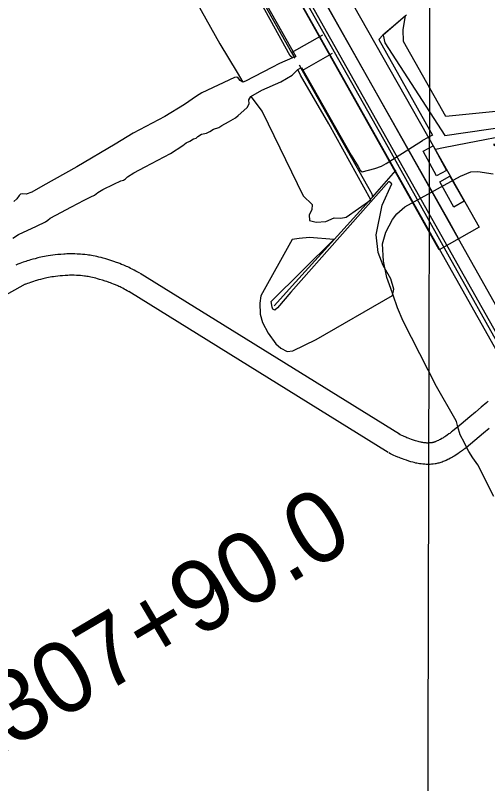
# Model space of a CAD drawing. Extents: x 3177185 to 3215018, y 812988 to 838321.
# Drawn here: x 3191262 to 3191925, y 825495 to 826573 of the extents above; entities that cross this region are included whole.
import ezdxf

# ---------------------------------------------------------------- set-up
doc = ezdxf.new("R2010")
doc.units = 0
for name, color, linetype in [('V-BLDG-OTLN', 7, 'Continuous'), ('V-BRDG-OTLN', 7, 'Continuous'), ('V-FLOD-BASE', 7, 'Continuous'), ('V-GRID-MAJR', 7, 'Continuous'), ('V-LEVE-TOET', 7, 'Continuous'), ('V-RAIL-TRAK', 7, 'Continuous'), ('V-RIVR-JETY', 7, 'Continuous'), ('V-ROAD-CNTR', 7, 'Continuous'), ('V-SURV-IDEN', 7, 'Continuous'), ('V-SURV-LINE', 7, 'Continuous'), ('V-TOPO-SHOR', 7, 'Continuous')]:
    doc.layers.add(name, color=color, linetype=linetype)

msp = doc.modelspace()

# ---------------------------------------------------------------- linework, layer by layer
at = {"layer": 'V-BLDG-OTLN'}
for points in [[(3191853.342, 826348.125), (3191834.697, 826382.585), (3191848.629, 826390.126), (3191867.278, 826355.664)], [(3191857.919, 826339.643), (3191872.198, 826347.675), (3191892.082, 826312.328), (3191877.801, 826304.296)]]:
    msp.add_lwpolyline(points, close=True, dxfattribs=at)
at = {"layer": 'V-BRDG-OTLN'}
msp.add_lwpolyline([(3189931.128, 829788.835), (3190041.103, 829594.308), (3190262.136, 829203.113), (3190443.982, 828880.4280000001), (3190572.68, 828651.763), (3190882.977, 828101.979), (3191302.909, 827356.358), (3191715.392, 826625.533), (3191850.532, 826386.759), (3191913.1350000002, 826276.1460000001), (3191857.18, 826244.404), (3191504.1350000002, 826872.585), (3191185.7430000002, 827436.355), (3190860.389, 828014.278), (3190535.683, 828590.2490000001), (3190389.4390000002, 828848.387), (3190198.296, 829187.503), (3189983.563, 829569.502), (3189815.178, 829866.551), (3189869.727, 829897.438)], close=True, dxfattribs=at)
msp.add_lwpolyline([(3189842.421, 829881.978), (3189906.728, 829766.487), (3190091.396, 829438.875), (3190276.556, 829111.594), (3190415.058, 828865.636), (3190768.106, 828239.242), (3190952.4020000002, 827910.9990000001), (3191133.947, 827589.914), (3191349.986, 827207.018), (3191641.818, 826689.277), (3191870.9790000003, 826283.448), (3191884.369, 826259.828)], dxfattribs=at)
at = {"layer": 'V-FLOD-BASE'}
for p, q in [((3191649.643, 826521.356), (3191693.649, 826546.165)), ((3191649.643, 826521.356), (3191654.1350000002, 826513.3520000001)), ((3191664.829, 826495.9890000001), (3191707.4220000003, 826520.448)), ((3191660.455, 826503.755), (3191664.829, 826495.9890000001))]:
    msp.add_line(p, q, dxfattribs=at)
for points in [[(3190314.173, 828890.916), (3190510.294, 828542.9940000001), (3190730.057, 828152.9400000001), (3191049.907, 827586.404), (3191280.358, 827177.3200000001), (3191576.724, 826651.285), (3191649.643, 826521.356)], [(3191664.829, 826495.9890000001), (3191762.482, 826322.716), (3191763.287, 826318.327)], [(3191850.532, 826386.759), (3191851.992, 826385.295), (3191863.3710000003, 826387.709), (3191896.6920000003, 826394.31), (3192023.1520000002, 826418.607), (3192066.715, 826427.301), (3192080.043, 826429.388)], [(3191625.213, 826165.849), (3191655.335, 826198.941), (3191718.997, 826268.851), (3191763.287, 826318.327), (3191796.014, 826355.638), (3191795.0470000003, 826354.958)]]:
    msp.add_lwpolyline(points, dxfattribs=at)
at = {"layer": 'V-GRID-MAJR'}
msp.add_spline([(3191823.847, 818374.883), (3191838.828, 824434.0750000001), (3191853.818, 830496.351), (3191868.808, 836558.667), (3191868.816, 836561.711)], degree=3, dxfattribs=at)
at = {"layer": 'V-LEVE-TOET'}
msp.add_lwpolyline([(3191933.722, 825898.231), (3191911.382, 825942.632), (3191904.576, 825952.231), (3191898.906, 825961.34), (3191895.342, 825967.197), (3191892.592, 825973.376), (3191886.599, 825984.761), (3191883.3710000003, 825995.816), (3191881.272, 826003.457), (3191879.005, 826007.361), (3191853.417, 826052.581), (3191806.631, 826143.985), (3191798.703, 826163.011), (3191792.563, 826180.732), (3191789.3310000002, 826190.1630000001), (3191783.673, 826205.286), (3191779.003, 826228.528), (3191777.2600000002, 826252.7440000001), (3191782.329, 826269.144), (3191791.3000000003, 826287.001), (3191797.489, 826294.951), (3191808.718, 826304.679), (3191886.953, 826347.755), (3191901.752, 826353.7390000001), (3191911.177, 826354.372), (3191932.782, 826350.755)], dxfattribs=at)
at = {"layer": 'V-RAIL-TRAK'}
for points in [[(3191871.696, 826233.868), (3191785.219, 826388.248), (3191407.875, 827056.285), (3191034.9080000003, 827717.65), (3190723.6380000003, 828268.084), (3190388.417, 828864.737)], [(3193727.307, 822943), (3193577.661, 823206.018), (3193415.878, 823494.571), (3193219.921, 823842.66), (3193027.524, 824182.939), (3192797.072, 824592.348), (3192558.2, 825016.721), (3192352.2, 825381.723), (3192184.2600000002, 825679.875), (3191974.37, 826050.574), (3191871.696, 826233.868)]]:
    msp.add_lwpolyline(points, dxfattribs=at)
at = {"layer": 'V-RIVR-JETY'}
for p, q in [((3191809.662, 826572.605), (3191778.235, 826545.731)), ((3191651.306, 826513.821), (3191651.294, 826513.831))]:
    msp.add_line(p, q, dxfattribs=at)
for points in [[(3191651.239, 826513.79), (3191647.901, 826516.692), (3191568.704, 826660.794), (3191407.398, 826948.171), (3191228.251, 827262.207), (3190970.738, 827718.264), (3190670.929, 828250.537), (3190397.24, 828734.5), (3190316.142, 828880.123)], [(3190290.572, 828778.2390000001), (3190397.9390000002, 828569.5970000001), (3190618.136, 828181.843), (3190879.796, 827718.289), (3191104.97, 827320.956), (3191323.508, 826935.701), (3191549.0870000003, 826533.373), (3191573.142, 826492.9720000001), (3191581.4020000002, 826479.777)], [(3191933.285, 826391.953), (3192060.863, 826312.2490000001), (3192152.944, 826383.2220000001), (3192074.849, 826448.688), (3192064.038, 826452.037), (3192054.883, 826451.638), (3192025.3370000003, 826447.116), (3191866.375, 826431.186), (3191807.077, 826536.56), (3191806.6920000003, 826553.618), (3191809.662, 826572.605)], [(3191778.235, 826545.731), (3191780.842, 826534.665), (3191865.058, 826404.699), (3192081.4620000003, 826435.915), (3192085.603, 826425.089), (3191933.285, 826391.953)], [(3191651.239, 826513.79), (3191632.96, 826505.6780000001), (3191622.225, 826500.1730000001)], [(3191622.225, 826500.1730000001), (3191584.816, 826480.746), (3191581.4020000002, 826479.777)], [(3191592.576, 826459.444), (3191608.497, 826438.4770000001), (3191666.107, 826320.211), (3191678.565, 826307.706), (3191678.1350000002, 826300.219), (3191674.377, 826293.569), (3191674.779, 826285.248), (3191684.345, 826283.149), (3191697.659, 826283.958), (3191709.734, 826289.344), (3191718.886, 826288.91), (3191726.378, 826290.145), (3191760.9560000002, 826314.626), (3191702.076, 826421.245), (3191662.2630000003, 826489.552), (3191658.491, 826497.099)], [(3191634.535, 826480.002), (3191650.477, 826489.3960000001), (3191657.5470000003, 826496.536), (3191658.491, 826497.099)], [(3191592.576, 826459.444), (3191608.028, 826468.191), (3191634.535, 826480.002)], [(3191650.538, 826258.513), (3191606.705, 826179.546), (3191605.024, 826169.564), (3191605.411, 826154.17), (3191608.716, 826142.099), (3191617.009, 826127.103), (3191627.384, 826112.524), (3191634.861, 826106.269), (3191643.588, 826101.675), (3191651.495, 826102.492), (3191684.392, 826118.242), (3191791.433, 826180.032), (3191793.5300000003, 826189.182), (3191788.9790000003, 826203.336), (3191778.614, 826222.077), (3191771.16, 826240.399), (3191768.71, 826265.366), (3191777.109, 826306.954), (3191790.478, 826336.886), (3191786.325, 826340.2220000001), (3191648.736, 826184.875), (3191629.972, 826162.859), (3191626.223, 826159.539), (3191623.312, 826160.7930000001), (3191622.487, 826163.7050000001), (3191621.252, 826171.6140000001), (3191709.201, 826258.8200000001), (3191675.065, 826261.46)], [(3191675.065, 826261.46), (3191660.502, 826260.24), (3191650.538, 826258.513)]]:
    msp.add_lwpolyline(points, dxfattribs=at)
at = {"layer": 'V-ROAD-CNTR'}
for points in [[(3186813.0193371, 835225.176522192), (3189830.7133017, 829864.116244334), (3191892.325178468, 826207.063558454)], [(3191436.466090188, 826211.367549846), (3191433.683095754, 826212.9725466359), (3191430.952101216, 826214.4835436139), (3191428.38510635, 826215.85054088), (3191425.9691111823, 826217.0905384), (3191423.696115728, 826218.2165361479), (3191421.561119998, 826219.239534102), (3191419.553124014, 826220.1735322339), (3191417.6321278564, 826221.0405305), (3191414.1221348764, 826222.5625274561), (3191410.99514113, 826223.8545248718), (3191408.247146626, 826224.939522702), (3191405.8351514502, 826225.858520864), (3191403.6841557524, 826226.65051928), (3191399.9971631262, 826227.954516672), (3191397.15016882, 826228.917514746), (3191392.9211772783, 826230.278512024), (3191388.613185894, 826231.593509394), (3191385.2601926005, 826232.551507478), (3191382.08519895, 826233.3905058), (3191379.1032049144, 826234.118504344), (3191376.298210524, 826234.751503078), (3191373.669215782, 826235.2985019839), (3191371.2002207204, 826235.773501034), (3191368.88022536, 826236.18550021), (3191366.709229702, 826236.5394995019), (3191364.6692337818, 826236.8474988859), (3191362.71523769, 826237.1164983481), (3191359.1782447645, 826237.546497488), (3191356.0372510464, 826237.862496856), (3191353.2892565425, 826238.091496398), (3191350.8852613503, 826238.253496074), (3191348.7442656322, 826238.368495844), (3191345.12527287, 826238.50049558), (3191342.3692783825, 826238.547495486), (3191340.269282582, 826238.552495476), (3191337.2042887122, 826238.5124955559), (3191334.154294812, 826238.4154957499), (3191331.874299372, 826238.3104959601), (3191329.6603038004, 826238.1854962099), (3191325.4773121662, 826237.8904968), (3191321.518320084, 826237.53549751), (3191317.807327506, 826237.1374983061), (3191314.326334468, 826236.7034991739), (3191311.06534099, 826236.2435000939), (3191308.0083471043, 826235.76550105), (3191305.144352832, 826235.2755020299), (3191302.458358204, 826234.7785030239), (3191299.942363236, 826234.2795040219), (3191297.586367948, 826233.7825050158), (3191295.3803723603, 826233.2915059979), (3191293.274376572, 826232.7995069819), (3191289.434384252, 826231.8395089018), (3191286.046391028, 826230.9265107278), (3191283.082396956, 826230.077512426), (3191280.492402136, 826229.2945139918), (3191278.2294066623, 826228.58051542), (3191276.217410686, 826227.9205167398), (3191272.80041752, 826226.746519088), (3191270.2044227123, 826225.8095209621), (3191268.234426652, 826225.0715224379), (3191265.347432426, 826223.948524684), (3191262.5504380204, 826222.811526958)], [(3191801.187360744, 825985.3460018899), (3191436.872089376, 826211.1245503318)], [(3191421.474120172, 826185.3816018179), (3191418.92512527, 826186.852598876), (3191416.6381298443, 826188.117596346), (3191414.48513415, 826189.2645940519), (3191412.461138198, 826190.3025919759), (3191410.552142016, 826191.2485900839), (3191408.753145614, 826192.111588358), (3191407.057149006, 826192.899586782), (3191405.492152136, 826193.6065853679), (3191402.428158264, 826194.9345827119), (3191399.759163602, 826196.036580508), (3191397.397168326, 826196.9695786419), (3191395.3091725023, 826197.7645770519), (3191393.498176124, 826198.432575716), (3191390.1931827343, 826199.60057338), (3191387.746187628, 826200.4275717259), (3191383.94519523, 826201.6525692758), (3191380.113202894, 826202.821566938), (3191377.308208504, 826203.6235653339), (3191374.69521373, 826204.312563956), (3191372.241218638, 826204.9125627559), (3191369.94022324, 826205.431561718), (3191367.77522757, 826205.8825608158), (3191365.746231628, 826206.2735600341), (3191363.846235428, 826206.6095593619), (3191362.0572390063, 826206.901558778), (3191360.383242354, 826207.153558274), (3191358.85524541, 826207.364557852), (3191355.8622513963, 826207.7285571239), (3191353.2892565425, 826207.9885566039), (3191351.039261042, 826208.1755562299), (3191349.071264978, 826208.307555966), (3191347.3902683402, 826208.398555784), (3191344.3252744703, 826208.5105555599), (3191342.077278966, 826208.547555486), (3191340.4272822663, 826208.552555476), (3191337.8782873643, 826208.518555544), (3191335.324292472, 826208.437555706), (3191333.4082963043, 826208.3485558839), (3191331.558300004, 826208.2455560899), (3191327.8713073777, 826207.984556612), (3191324.458314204, 826207.6795572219), (3191321.263320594, 826207.33555791), (3191318.274326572, 826206.9635586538), (3191315.4773321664, 826206.5695594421), (3191312.856337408, 826206.159560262), (3191310.404342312, 826205.7395611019), (3191308.1083469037, 826205.3145619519), (3191305.958351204, 826204.8875628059), (3191303.942355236, 826204.4625636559), (3191302.052359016, 826204.041564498), (3191300.3223624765, 826203.6375653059), (3191296.974369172, 826202.801566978), (3191294.082374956, 826202.0225685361), (3191291.5563800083, 826201.2975699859), (3191289.348384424, 826200.6305713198), (3191287.417388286, 826200.0205725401), (3191285.7613915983, 826199.4785736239), (3191282.768397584, 826198.45057568), (3191280.562401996, 826197.6535772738), (3191278.934405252, 826197.0435784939), (3191276.431410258, 826196.0705804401), (3191273.844415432, 826195.019582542)], [(3191892.325178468, 826207.063558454), (3193654.2206546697, 823085.5218015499)], [(3191275.5274120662, 826195.8285809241), (3190696.3915703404, 825871.460229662)], [(3191785.383392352, 825959.8460528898), (3191421.0681209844, 826185.624601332)], [(3191925.8871113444, 826031.711909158), (3191924.937113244, 826030.8249109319), (3191923.9301152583, 826029.9379127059), (3191916.116130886, 826023.3069259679), (3191908.185146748, 826016.639939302), (3191900.1021629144, 826009.892952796), (3191887.9281872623, 825999.7889730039), (3191875.750211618, 825989.728993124), (3191874.34421443, 825988.58599541), (3191873.055217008, 825987.5699974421), (3191871.833219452, 825986.6339993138), (3191870.715221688, 825985.800000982), (3191868.487226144, 825984.2050041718), (3191866.55423001, 825982.8900068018), (3191864.83923344, 825981.777009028), (3191863.328236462, 825980.8360109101), (3191861.998239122, 825980.040012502), (3191860.862241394, 825979.384013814), (3191858.733245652, 825978.2100161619), (3191857.165248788, 825977.3930177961), (3191856.01925108, 825976.8200189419), (3191854.200254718, 825975.954020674), (3191852.425258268, 825975.1600222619), (3191851.71925968, 825974.868022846), (3191851.063260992, 825974.6230233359), (3191850.4092623, 825974.402023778), (3191849.757263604, 825974.203024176), (3191849.111264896, 825974.02602453), (3191848.47426617, 825973.8700248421), (3191847.8382674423, 825973.7320251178), (3191847.202268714, 825973.6090253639), (3191846.6572698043, 825973.517025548), (3191845.33427245, 825973.335025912), (3191844.141274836, 825973.219026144), (3191842.9892771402, 825973.1480262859), (3191841.8832793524, 825973.115026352), (3191840.8242814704, 825973.1120263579), (3191839.8222834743, 825973.13602631), (3191838.8672853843, 825973.1810262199), (3191837.953287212, 825973.2430260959), (3191837.1592888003, 825973.3120259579), (3191835.462292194, 825973.504025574), (3191834.0292950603, 825973.710025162), (3191832.76929758, 825973.9240247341), (3191831.666299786, 825974.1360243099), (3191830.7513016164, 825974.3290239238), (3191828.98430515, 825974.744023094), (3191827.7823075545, 825975.0580224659), (3191825.866311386, 825975.609021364), (3191823.938315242, 825976.227020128), (3191820.807321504, 825977.2920179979), (3191818.0403270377, 825978.2580160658), (3191815.666331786, 825979.1130143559), (3191813.626335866, 825979.875012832), (3191811.865339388, 825980.555011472), (3191810.2723425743, 825981.1910102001)], [(3191927.44910822, 825993.6419852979), (3191919.2941245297, 825986.8349989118), (3191907.062148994, 825976.6830192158), (3191894.766173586, 825966.525039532), (3191893.09417693, 825965.1660422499), (3191891.4631801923, 825963.880044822), (3191889.9171832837, 825962.69604719), (3191888.413186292, 825961.57604943), (3191885.6591918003, 825959.603053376), (3191883.1581968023, 825957.902056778), (3191880.935201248, 825956.459059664), (3191878.958205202, 825955.228062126), (3191877.202208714, 825954.1780642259), (3191875.610211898, 825953.2580660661), (3191872.911217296, 825951.770069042), (3191870.8072215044, 825950.6730712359), (3191869.173224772, 825949.8560728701), (3191866.776229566, 825948.7160751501), (3191864.2812345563, 825947.5980773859), (3191862.705237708, 825946.948078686), (3191861.123240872, 825946.355079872), (3191859.5852439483, 825945.8360809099), (3191858.093246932, 825945.38108182), (3191856.641249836, 825944.984082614), (3191855.230252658, 825944.6380833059), (3191853.868255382, 825944.3420838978), (3191852.558258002, 825944.089084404), (3191851.205260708, 825943.8590848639), (3191848.8242654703, 825943.533085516), (3191846.517270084, 825943.309085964), (3191844.36927438, 825943.1760862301), (3191842.367278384, 825943.1150863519), (3191840.5042821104, 825943.1120863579), (3191838.762285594, 825943.152086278), (3191837.141288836, 825943.229086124), (3191835.641291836, 825943.3310859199), (3191834.1732947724, 825943.458085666), (3191831.638299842, 825943.74608509), (3191829.3813043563, 825944.0700844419), (3191827.42930826, 825944.4020837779), (3191825.7383116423, 825944.7260831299), (3191824.2213146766, 825945.0470824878), (3191821.7703195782, 825945.622081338), (3191819.84432343, 825946.124080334), (3191817.13432885, 825946.9050787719), (3191814.528334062, 825947.7410771), (3191811.037341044, 825948.9280747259), (3191808.01434709, 825949.982072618), (3191805.336352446, 825950.947070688), (3191802.972357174, 825951.829068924), (3191800.893361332, 825952.6330673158), (3191799.142364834, 825953.3330659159)], [(3191810.5053421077, 825981.0960103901), (3191807.747347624, 825982.2520080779), (3191805.851351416, 825983.095006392), (3191804.5003541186, 825983.723005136), (3191802.4293582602, 825984.739003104), (3191800.2473626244, 825985.8830008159)], [(3191798.9093653, 825953.4280657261), (3191795.855371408, 825954.7080631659), (3191793.431376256, 825955.785061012), (3191791.566379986, 825956.6530592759), (3191788.8593854, 825957.9810566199), (3191786.323390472, 825959.3090539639)]]:
    msp.add_lwpolyline(points, dxfattribs=at)
at = {"layer": 'V-SURV-LINE'}
for points in [[(3189802.9949350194, 829952.0952459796), (3191996.6094444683, 826059.8623800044)], [(3191970.4710434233, 826045.1387922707), (3189776.856314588, 829937.3720475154)]]:
    msp.add_lwpolyline(points, dxfattribs=at)
at = {"layer": 'V-TOPO-SHOR'}
for p, q in [((3191777.951, 826545.487), (3191772.519, 826539.241)), ((3191655.5640000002, 826515.709), (3191651.239, 826513.79)), ((3191589.805, 826454.738), (3191592.576, 826459.444)), ((3191782.419, 826365.54), (3191833.429, 826397.574))]:
    msp.add_line(p, q, dxfattribs=at)
for points in [[(3190317.059, 828891.16), (3190656.339, 828287.702), (3190859.5870000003, 827927.74), (3191060.5670000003, 827572.657), (3191269.965, 827200.335), (3191547.221, 826707.971), (3191655.5640000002, 826515.709)], [(3191809.662, 826572.605), (3191789.995, 826555.703), (3191777.951, 826545.487)], [(3191810.989, 826574.024), (3191809.662, 826572.605)], [(3191772.519, 826539.241), (3191847.884, 826405.074), (3191833.429, 826397.574)], [(3191651.239, 826513.79), (3191632.96, 826505.6780000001), (3191622.225, 826500.1730000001)], [(3191622.225, 826500.1730000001), (3191584.816, 826480.746), (3191581.4020000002, 826479.777)], [(3191634.535, 826480.002), (3191650.477, 826489.3960000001), (3191657.5470000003, 826496.536), (3191658.491, 826497.099)], [(3191658.491, 826497.099), (3191663.4960000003, 826500.0970000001), (3191733.624, 826377.289), (3191743.18, 826361.3470000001), (3191746.094, 826355.98), (3191748.853, 826353.7000000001), (3191766.736, 826358.216), (3191776.165, 826361.612), (3191782.419, 826365.54)], [(3191581.4020000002, 826479.777), (3191577.345, 826481.735), (3191574.103, 826486.128), (3191572.315, 826486.456), (3191569.552, 826485.974), (3191523.853, 826464.612), (3191516.372, 826460.0750000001), (3191499.126, 826448.41), (3191471.633, 826431.237), (3191453.906, 826422.007), (3191427.069, 826407.759), (3191401.6920000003, 826392.532), (3191348.012, 826360.6240000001), (3191300.355, 826333.902), (3191284.901, 826324.995), (3191276.934, 826322.2490000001), (3191272.3850000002, 826322.906), (3191268.81, 826322.263), (3191266.858, 826320.318), (3191263.598, 826315.611), (3191259.6920000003, 826312.044)], [(3191592.576, 826459.444), (3191608.028, 826468.191), (3191634.535, 826480.002)], [(3191258.133, 826260.7000000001), (3191266.2660000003, 826265.7220000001), (3191291.637, 826277.537), (3191303.835, 826283.525), (3191307.414, 826285.956), (3191310.8310000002, 826288.549), (3191318.801, 826292.76), (3191340.758, 826304.581), (3191358.162, 826313.971), (3191367.757, 826318.503), (3191372.961, 826320.768), (3191377.356, 826324.498), (3191384.511, 826328.708), (3191399.964, 826336.317), (3191409.72, 826340.849), (3191413.46, 826341.816), (3191416.389, 826343.9230000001), (3191419.1550000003, 826346.518), (3191428.103, 826352.512), (3191444.204, 826360.77), (3191479.823, 826379.226), (3191496.744, 826390.568), (3191501.4620000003, 826394.2980000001), (3191506.828, 826396.886), (3191511.872, 826399.8030000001), (3191515.936, 826400.931), (3191518.215, 826403.202), (3191523.257, 826406.442), (3191530.085, 826408.054), (3191534.802, 826410.483), (3191540.008, 826413.397), (3191547.323, 826416.1460000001), (3191551.555, 826418.9), (3191561.149, 826423.756), (3191570.91, 826429.589), (3191574.654, 826432.995), (3191582.465, 826439.804), (3191587.186, 826444.019), (3191589.957, 826449.215), (3191589.805, 826454.738)]]:
    msp.add_lwpolyline(points, dxfattribs=at)

# ---------------------------------------------------------------- texts
at = {"layer": 'V-SURV-IDEN'}
msp.add_text('1307+90.0', height=100, rotation=30.635833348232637, dxfattribs=at).set_placement((3191193.7421761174, 825506.7396227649))

doc.saveas('drawing.dxf')
